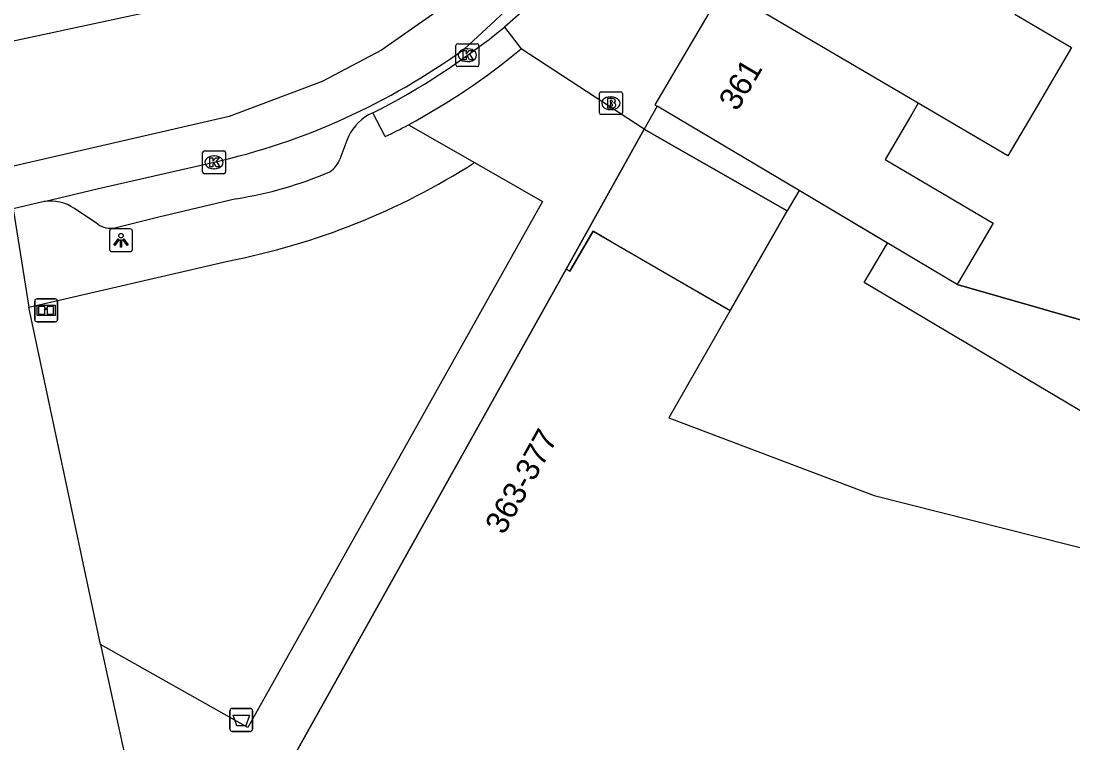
# Model space of a CAD drawing. Extents: x 160557 to 161245, y 385330 to 386505.
# Drawn here: x 160787.27 to 160833.24, y 385700.75 to 385732.31 of the extents above; entities that cross this region are included whole.
import ezdxf

# ---------------------------------------------------------------- set-up
doc = ezdxf.new("R2010")
doc.units = 0
for name, color, linetype in [('IMGEO_Afvalbak', 7, 'Continuous'), ('IMGEO_Brandkraan', 7, 'Continuous'), ('IMGEO_Informatiebord', 7, 'Continuous'), ('IMGEO_Kolk', 7, 'Continuous'), ('IMGEO_Lichtpunt', 7, 'Continuous'), ('IMGEO_Muur', 7, 'Continuous'), ('IMGEO_Pand', 7, 'Continuous'), ('IMGEO_Pand_nummerreeks', 7, 'Continuous'), ('IMGEO_Pand_overbouw', 7, 'Continuous'), ('IMGEO_Rijbaan_lokaal_gesloten', 7, 'Continuous'), ('IMGEO_Rijbaan_lokaal_open', 7, 'Continuous'), ('IMGEO_Voetpad_open', 7, 'Continuous')]:
    doc.layers.add(name, color=color, linetype=linetype)

msp = doc.modelspace()

# ---------------------------------------------------------------- linework, layer by layer
at = {"layer": 'IMGEO_Afvalbak'}
for p, q in [((160796.402, 385701.36), (160796.402, 385702.16)), ((160796.402, 385702.16), (160796.402, 385701.36)), ((160796.502, 385702.26), (160797.292, 385702.26)), ((160797.292, 385702.26), (160796.502, 385702.26)), ((160797.392, 385702.16), (160797.392, 385701.36)), ((160797.392, 385701.36), (160797.392, 385702.16)), ((160797.292, 385701.26), (160796.502, 385701.26)), ((160796.502, 385701.26), (160797.292, 385701.26))]:
    msp.add_line(p, q, dxfattribs=at)
msp.add_lwpolyline([(160796.545, 385701.974), (160797.249, 385701.974), (160797.1, 385701.504), (160796.694, 385701.504), (160796.545, 385701.974)], dxfattribs=at)
for centre, start, end in [((160796.502, 385702.16), 90, 180), ((160796.502, 385702.16), 90, 180), ((160797.292, 385702.16), 0, 90), ((160797.292, 385702.16), 360, 90), ((160796.502, 385701.36), 180, 270), ((160796.502, 385701.36), 180, 270), ((160797.292, 385701.36), 270, 0), ((160797.292, 385701.36), 270, 0)]:
    msp.add_arc(centre, 0.1, start, end, dxfattribs=at)
at = {"layer": 'IMGEO_Brandkraan'}
for p, q in [((160812.546, 385728.296), (160812.546, 385729.148)), ((160812.621, 385729.222), (160813.473, 385729.222)), ((160813.547, 385729.148), (160813.547, 385728.296)), ((160813.034, 385729.002), (160813.059, 385729.002)), ((160813.473, 385728.222), (160812.621, 385728.222)), ((160813.057, 385728.442), (160813.032, 385728.442))]:
    msp.add_line(p, q, dxfattribs=at)
for points in [[(160812.546, 385728.296), (160812.546, 385729.148)], [(160812.621, 385729.222), (160813.473, 385729.222)], [(160813.547, 385729.148), (160813.547, 385728.296)], [(160812.894, 385728.922), (160812.894, 385728.522), (160813.107, 385728.522)], [(160813.125, 385728.922), (160812.894, 385728.922)], [(160813.073, 385728.841), (160813.019, 385728.841), (160813.019, 385728.765)], [(160813.019, 385728.765), (160813.072, 385728.765)], [(160813.081, 385728.689), (160813.019, 385728.689), (160813.019, 385728.608)], [(160813.473, 385728.222), (160812.621, 385728.222)], [(160813.019, 385728.608), (160813.081, 385728.608)]]:
    msp.add_lwpolyline(points, dxfattribs=at)
for centre, radius, start, end in [((160812.623, 385729.146), 0.0765, 91.552, 178.448), ((160812.623, 385729.146), 0.0765, 91.552, 178.448), ((160813.471, 385729.146), 0.0765, 1.552, 88.448), ((160813.471, 385729.146), 0.0765, 1.552, 88.448), ((160813.074, 385728.803), 0.0379, 267.8285, 90.9355), ((160813.082, 385728.648), 0.0404, 269.8759, 90.5077), ((160813.129, 385728.777), 0.145, 59.4692, 91.5367), ((160813.154, 385728.824), 0.0922, 285.5137, 58.1501), ((160813.159, 385728.632), 0.105, 301.3115, 78.989), ((160812.623, 385728.298), 0.0765, 181.552, 268.448), ((160812.623, 385728.298), 0.0765, 181.552, 268.448), ((160813.113, 385728.773), 0.251, 268.6676, 293.5347), ((160813.471, 385728.298), 0.0765, 271.552, 358.448), ((160813.471, 385728.298), 0.0765, 271.552, 358.448)]:
    msp.add_arc(centre, radius, start, end, dxfattribs=at)
for centre, major_axis, ratio, start_param, end_param in [((160813.033, 385728.722), (-0.387, 0.002), 0.722429, 4.712389, 7.853982), ((160813.058, 385728.722), (-0.39, 0.002), 0.717154, 1.570796, 4.712389)]:
    msp.add_ellipse(centre, major_axis=major_axis, ratio=ratio, start_param=start_param, end_param=end_param, dxfattribs=at)
at = {"layer": 'IMGEO_Informatiebord'}
for p, q in [((160787.872, 385719.266), (160787.872, 385720.066)), ((160787.872, 385720.066), (160787.872, 385719.266)), ((160787.972, 385720.166), (160788.762, 385720.166)), ((160788.762, 385720.166), (160787.972, 385720.166)), ((160788.862, 385720.066), (160788.862, 385719.266)), ((160788.862, 385719.266), (160788.862, 385720.066)), ((160788.762, 385719.166), (160787.972, 385719.166)), ((160787.972, 385719.166), (160788.762, 385719.166))]:
    msp.add_line(p, q, dxfattribs=at)
for points in [[(160787.973, 385719.898), (160788.761, 385719.898), (160788.761, 385719.434), (160787.973, 385719.434), (160787.973, 385719.898)], [(160788.038, 385719.833), (160788.038, 385719.499), (160788.313, 385719.499), (160788.314, 385719.712), (160788.418, 385719.713), (160788.419, 385719.499), (160788.696, 385719.499), (160788.696, 385719.833), (160788.42, 385719.833), (160788.42, 385719.753), (160788.314, 385719.753), (160788.314, 385719.833), (160788.038, 385719.833)]]:
    msp.add_lwpolyline(points, dxfattribs=at)
for centre, start, end in [((160787.972, 385720.066), 90, 180), ((160787.972, 385720.066), 90, 180), ((160788.762, 385720.066), 0, 90), ((160788.762, 385720.066), 360, 90), ((160787.972, 385719.266), 180, 270), ((160787.972, 385719.266), 180, 270), ((160788.762, 385719.266), 270, 0), ((160788.762, 385719.266), 270, 0)]:
    msp.add_arc(centre, 0.1, start, end, dxfattribs=at)
at = {"layer": 'IMGEO_Kolk'}
for p, q in [((160806.276, 385730.396), (160806.276, 385731.248)), ((160806.351, 385731.322), (160807.203, 385731.322)), ((160806.764, 385731.102), (160806.789, 385731.102)), ((160807.277, 385731.248), (160807.277, 385730.396)), ((160806.787, 385730.542), (160806.762, 385730.542)), ((160807.203, 385730.322), (160806.351, 385730.322)), ((160795.207, 385725.712), (160795.207, 385726.564)), ((160795.282, 385726.638), (160796.134, 385726.638)), ((160795.695, 385726.418), (160795.72, 385726.418)), ((160796.208, 385726.564), (160796.208, 385725.712)), ((160796.134, 385725.638), (160795.282, 385725.638)), ((160795.718, 385725.858), (160795.693, 385725.858))]:
    msp.add_line(p, q, dxfattribs=at)
for points in [[(160806.276, 385730.396), (160806.276, 385731.248)], [(160806.351, 385731.322), (160807.203, 385731.322)], [(160806.597, 385731.022), (160806.72, 385731.022), (160806.72, 385730.871), (160806.85, 385731.022), (160807.014, 385731.022), (160806.868, 385730.871), (160807.021, 385730.622), (160806.869, 385730.622), (160806.784, 385730.786), (160806.72, 385730.719), (160806.72, 385730.622), (160806.597, 385730.622), (160806.597, 385731.022)], [(160807.277, 385731.248), (160807.277, 385730.396)], [(160807.203, 385730.322), (160806.351, 385730.322)], [(160795.207, 385725.712), (160795.207, 385726.564)], [(160795.282, 385726.638), (160796.134, 385726.638)], [(160796.208, 385726.564), (160796.208, 385725.712)], [(160795.528, 385726.338), (160795.651, 385726.338), (160795.651, 385726.187), (160795.781, 385726.338), (160795.945, 385726.338), (160795.799, 385726.187), (160795.952, 385725.938), (160795.8, 385725.938), (160795.715, 385726.102), (160795.651, 385726.035), (160795.651, 385725.938), (160795.528, 385725.938), (160795.528, 385726.338)], [(160796.134, 385725.638), (160795.282, 385725.638)]]:
    msp.add_lwpolyline(points, dxfattribs=at)
for centre, start, end in [((160806.353, 385731.246), 91.552, 178.448), ((160806.353, 385731.246), 91.552, 178.448), ((160807.201, 385731.246), 1.552, 88.448), ((160807.201, 385731.246), 1.552, 88.448), ((160806.353, 385730.398), 181.552, 268.448), ((160806.353, 385730.398), 181.552, 268.448), ((160807.201, 385730.398), 271.552, 358.448), ((160807.201, 385730.398), 271.552, 358.448), ((160795.284, 385726.562), 91.552, 178.448), ((160795.284, 385726.562), 91.552, 178.448), ((160796.132, 385726.562), 1.552, 88.448), ((160796.132, 385726.562), 1.552, 88.448), ((160795.284, 385725.714), 181.552, 268.448), ((160795.284, 385725.714), 181.552, 268.448), ((160796.132, 385725.714), 271.552, 358.448), ((160796.132, 385725.714), 271.552, 358.448)]:
    msp.add_arc(centre, 0.0765, start, end, dxfattribs=at)
for centre, major_axis, ratio, start_param, end_param in [((160806.763, 385730.822), (-0.387, 0.002), 0.722429, 4.712389, 7.853982), ((160806.788, 385730.822), (-0.39, 0.002), 0.717154, 1.570796, 4.712389), ((160795.694, 385726.138), (-0.387, 0.002), 0.722429, 4.712389, 7.853982), ((160795.719, 385726.138), (-0.39, 0.002), 0.717154, 1.570796, 4.712389)]:
    msp.add_ellipse(centre, major_axis=major_axis, ratio=ratio, start_param=start_param, end_param=end_param, dxfattribs=at)
at = {"layer": 'IMGEO_Lichtpunt'}
for p, q in [((160791.14, 385723.133), (160791.14, 385722.326)), ((160791.14, 385723.133), (160791.14, 385722.326)), ((160792.042, 385723.228), (160791.234, 385723.228)), ((160792.042, 385723.228), (160791.234, 385723.228)), ((160792.136, 385722.326), (160792.136, 385723.133)), ((160792.136, 385722.326), (160792.136, 385723.133)), ((160791.234, 385722.232), (160792.042, 385722.232)), ((160791.234, 385722.232), (160792.042, 385722.232))]:
    msp.add_line(p, q, dxfattribs=at)
for points in [[(160791.514, 385722.797), (160791.553, 385722.769), (160791.365, 385722.507), (160791.327, 385722.534), (160791.514, 385722.797)], [(160791.616, 385722.749), (160791.663, 385722.749), (160791.663, 385722.427), (160791.616, 385722.427), (160791.616, 385722.749)], [(160791.726, 385722.769), (160791.764, 385722.796), (160791.951, 385722.534), (160791.912, 385722.506), (160791.726, 385722.769)]]:
    msp.add_lwpolyline(points, dxfattribs=at)
msp.add_circle((160791.639, 385722.931), 0.0994, dxfattribs=at)
for centre, start, end in [((160791.234, 385723.133), 90, 180), ((160791.234, 385723.133), 90, 180), ((160792.042, 385723.133), 0, 90), ((160792.042, 385723.133), 0, 90), ((160791.234, 385722.326), 180, 270), ((160791.234, 385722.326), 180, 270), ((160792.042, 385722.326), 270, 0), ((160792.042, 385722.326), 270, 360)]:
    msp.add_arc(centre, 0.0946, start, end, dxfattribs=at)
at = {"layer": 'IMGEO_Muur'}
msp.add_lwpolyline([(160856.562, 385712.649), (160828.176, 385720.801)], dxfattribs=at)
at = {"layer": 'IMGEO_Pand'}
for points in [[(160817.958, 385733.74), (160814.959, 385728.649), (160815.065, 385728.586)], [(160826.479, 385728.719), (160817.958, 385733.74)], [(160830.7, 385732.61), (160833.175, 385731.152), (160831.67, 385728.598), (160830.385, 385726.417), (160826.479, 385728.719)], [(160826.479, 385728.719), (160826.198, 385728.242), (160825.026, 385726.254), (160829.75, 385723.471), (160828.234, 385720.899), (160828.176, 385720.801)], [(160815.065, 385728.586), (160814.495, 385727.589)], [(160821.266, 385724.904), (160815.065, 385728.586)], [(160814.495, 385727.589), (160815.364, 385727.093), (160820.756, 385724.011)], [(160821.266, 385724.904), (160820.756, 385724.011)], [(160828.176, 385720.801), (160821.266, 385724.904)], [(160818.265, 385719.655), (160813.137, 385722.623), (160812.272, 385723.124), (160811.259, 385721.375), (160811.085, 385721.473)], [(160799.242, 385700.242), (160811.085, 385721.473)], [(160818.265, 385719.655), (160815.584, 385714.965), (160824.547, 385711.575), (160847.383, 385705.807), (160851.659, 385703.57)]]:
    msp.add_lwpolyline(points, dxfattribs=at)
at = {"layer": 'IMGEO_Pand_overbouw'}
msp.add_lwpolyline([(160845.865, 385707.972), (160824.111, 385720.889), (160825.132, 385722.609), (160821.266, 385724.904), (160815.065, 385728.586), (160814.495, 385727.589), (160811.085, 385721.473), (160799.242, 385700.242), (160807.995, 385695.338), (160812.372, 385675.602), (160812.932, 385673.076), (160807.713, 385671.926), (160800.168, 385670.228), (160806.16, 385643.282)], dxfattribs=at)
msp.add_lwpolyline([(160814.495, 385727.589), (160811.085, 385721.473), (160811.259, 385721.375), (160812.272, 385723.124), (160818.265, 385719.655), (160820.756, 385724.011), (160815.364, 385727.093)], close=True, dxfattribs=at)
at = {"layer": 'IMGEO_Rijbaan_lokaal_gesloten'}
for points in [[(160785.368, 385731.122), (160785.425, 385731.134), (160792.717, 385732.681), (160793.868, 385732.951), (160797.144, 385733.839), (160800.052, 385735.188), (160802.996, 385737.152), (160805.812, 385739.758), (160807.834, 385742.548), (160810.143, 385746.407), (160821.517, 385765.643)], [(160826.079, 385762.941), (160814.174, 385742.894), (160812.627, 385740.241), (160810.876, 385737.835), (160808.89, 385735.618), (160806.707, 385733.629), (160803.02, 385731.041), (160800.425, 385729.673), (160796.373, 385728.143), (160786.566, 385725.887), (160786.538, 385725.881)], [(160806.634, 385731.089), (160809.373, 385733.642), (160810.325, 385734.578), (160811.233, 385735.551), (160812.097, 385736.559), (160812.914, 385737.599), (160813.682, 385738.667), (160814.4, 385739.76), (160815.067, 385740.874), (160820.43, 385750), (160825.271, 385758.149), (160827.585, 385762.049)], [(160788.279, 385724.419), (160790.656, 385724.991), (160795.707, 385726.14)], [(160788.279, 385724.419), (160786.933, 385724.11)]]:
    msp.add_lwpolyline(points, dxfattribs=at)
msp.add_arc((160789.017, 385755.448), 30.061, 282.8578, 305.8752, dxfattribs=at)
at = {"layer": 'IMGEO_Rijbaan_lokaal_open'}
for points in [[(160811.085, 385721.473), (160814.495, 385727.589)], [(160820.756, 385724.011), (160818.265, 385719.655)], [(160828.176, 385720.801), (160856.562, 385712.649)]]:
    msp.add_lwpolyline(points, dxfattribs=at)
at = {"layer": 'IMGEO_Voetpad_open'}
for points in [[(160809.132, 385732.691), (160808.394, 385732.048)], [(160808.394, 385732.048), (160809.129, 385731.098)], [(160814.495, 385727.589), (160809.129, 385731.098)], [(160802.648, 385728.294), (160802.457, 385728.213)], [(160803.188, 385727.261), (160802.648, 385728.294)], [(160804.196, 385727.777), (160807.083, 385726.127)], [(160801.511, 385727.097), (160801.2, 385726.278)], [(160807.083, 385726.127), (160810.062, 385724.425), (160797.182, 385701.424), (160790.739, 385705.06)], [(160796.671, 385724.545), (160793.295, 385723.736), (160791.372, 385723.26)], [(160786.933, 385724.11), (160787.609, 385719.8)], [(160790.624, 385723.428), (160789.601, 385724.118)], [(160787.609, 385719.8), (160796.304, 385721.821)], [(160790.739, 385705.06), (160787.609, 385719.8)], [(160790.739, 385705.06), (160792.124, 385698.729)]]:
    msp.add_lwpolyline(points, dxfattribs=at)
for centre, radius, start, end in [((160787.733, 385757.398), 32.703, 297.134, 309.1811), ((160790.152, 385753.963), 29.714, 298.2064, 309.6922), ((160803.534, 385726.341), 2.16, 119.9138, 159.5123), ((160791.139, 385752.042), 27.555, 295.9307, 298.2855), ((160790.483, 385752.036), 30.771, 280.9042, 302.6472), ((160800.121, 385726.678), 1.151, 304.042, 339.6801), ((160793.962, 385741.648), 17.317, 278.9993, 293.1316), ((160788.558, 385722.592), 1.848, 55.657, 98.6896), ((160791.232, 385724.386), 1.135, 237.5973, 277.0857)]:
    msp.add_arc(centre, radius, start, end, dxfattribs=at)

# ---------------------------------------------------------------- texts
at = {"layer": 'IMGEO_Pand_nummerreeks'}
for s, rotation, p in [('361', 59.3355, (160818.563, 385728.331)), ('363-377', 60.7736, (160808.368, 385709.811))]:
    msp.add_text(s, height=1, rotation=rotation, dxfattribs=at).set_placement(p)

doc.saveas('drawing.dxf')
